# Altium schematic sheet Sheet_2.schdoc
size 305 x 189 mm
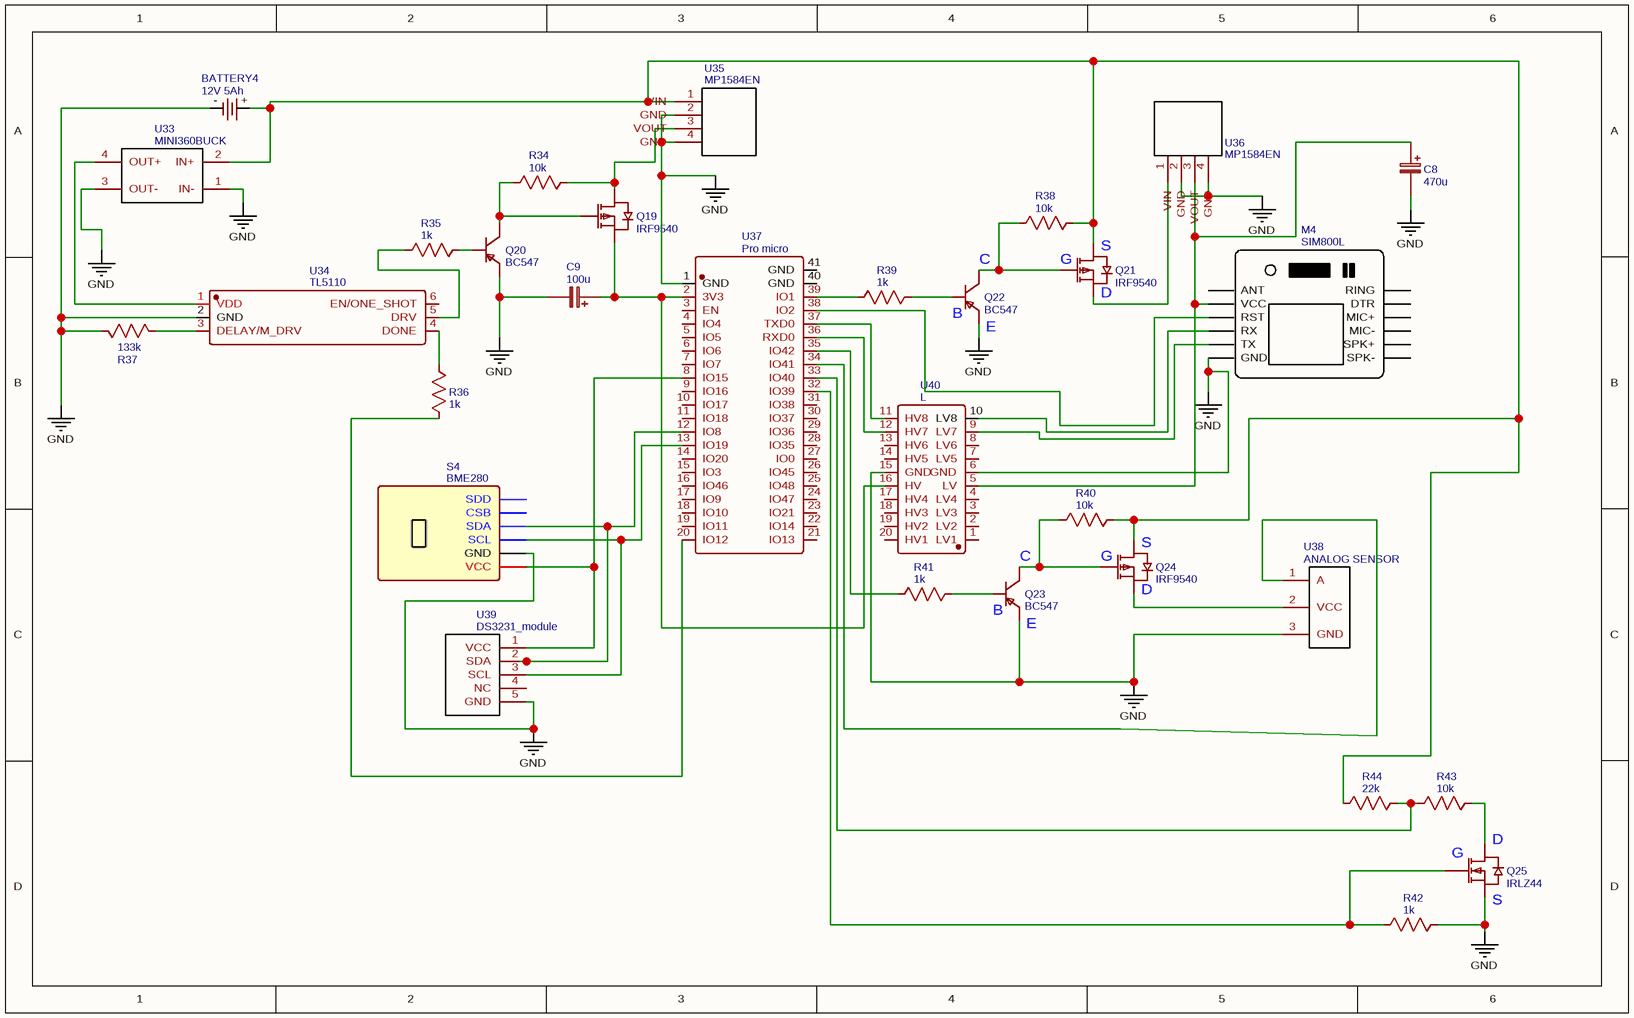
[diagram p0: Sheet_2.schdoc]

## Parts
BATTERY4  12V 5Ah  [BATTERY-SMD-MY-2032]
C8  470u  [CASE-A_3216]
C9  100u  [CASE-A_3216]
M4  SIM800L  [SIM800LMODULE_SIM800LMODULE]
Q19  IRF9540  [TO-263-2_L10.0-W9.1-P5.08-LS15.2-BR]
Q20  BC547  [SOT-23-3_L2.9-W1.6-P1.90-LS2.8-TR-CW]
Q21  IRF9540  [TO-263-2_L10.0-W9.1-P5.08-LS15.2-BR]
Q22  BC547  [SOT-23-3_L2.9-W1.6-P1.90-LS2.8-TR-CW]
Q23  BC547  [SOT-23-3_L2.9-W1.6-P1.90-LS2.8-TR-CW]
Q24  IRF9540  [TO-263-2_L10.0-W9.1-P5.08-LS15.2-BR]
Q25  IRLZ44  [TO-220-3_L10.0-W4.5-P2.54-T]
R34  10k  [R0603]
R35  1k  [R0603]
R36  1k  [R0603]
R37  133k  [R0603]
R38  10k  [R0603]
R39  1k  [R0603]
R40  10k  [R0603]
R41  1k  [R0603]
R42  1k  [R0603]
R43  10k  [R0603]
R44  22k  [R0603]
S4  BME280  [BME280]
U33  MINI360BUCK  [MINI360BUCK]
U34  TL5110  [TSOT-23-6_L2.9-W1.6-P0.95-LS2.8-BR]
U35  MP1584EN  [MP1584EN]
U36  MP1584EN  [MP1584EN]
U37  Pro micro  [WIRELM-SMD_ESP32-S3-WROOM-1U]
U38  ANALOG SENSOR  [ANALOG SENSOR V1]
U39  DS3231_module  [DS3231]
U40  L  [MPN-TH-20_L28.0-W14.0-P2.54-BL]

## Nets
GND: BATTERY4.-(BAT-) C8.2 C9.2 M4.6(GND) Q20.1(E) Q22.1(E) Q23.1(E) Q25.3(S) R37.1 R42.2 S4.2(GND) U33.1(IN-) U33.3(OUT-) U34.2(GND) U35.4(GND) U36.2(GND) U36.4(GND) U37.1(GND) U38.3(GND) U39.5(GND) U40.6(GND) U40.15(GND)
NetBATTERY4_+: BATTERY4.+(BAT+) Q21.4(D) Q24.4(D) R38.1 R40.1 R44.1 U33.2(IN+) U35.1(VIN)
NetC8_1: C8.1 M4.2(VCC) U36.3(VOUT) U40.5(LV)
NetC9_1: C9.1 Q19.3(S) U37.2(3V3) U40.16(HV)
NetM4_3: M4.3(RST) U37.38(IO2)
NetM4_4: M4.4(RX) U40.10(LV8)
NetM4_5: M4.5(TX) U40.9(LV7)
NetQ19_1: Q19.1(G) Q20.3(C) R34.2
NetQ19_4: Q19.4(D) R34.1 U35.3(VOUT)
NetQ20_2: Q20.2(B) R35.1
NetQ21_1: Q21.1(G) Q22.3(C) R38.2
NetQ21_3: Q21.3(S) U36.1(VIN)
NetQ22_2: Q22.2(B) R39.2
NetQ23_2: Q23.2(B) R41.2
NetQ23_3: Q23.3(C) Q24.1(G) R40.2
NetQ24_3: Q24.3(S) U38.2(VCC)
NetQ25_1: Q25.1(G) R42.1 U37.32(IO39)
NetQ25_2: Q25.2(D) R43.2
NetR35_2: R35.2 U34.5(DRV)
NetR36_1: R36.1 U34.4(DONE)
NetR36_2: R36.2 U37.20(IO12)
NetR37_2: R37.2 U34.3(DELAY/M_DRV)
NetR39_1: R39.1 U37.39(IO1)
NetR41_1: R41.1 U37.35(IO42)
NetR43_1: R43.1 R44.2 U37.33(IO40)
NetS4_1: S4.1(VCC) U37.8(IO15) U39.1(VCC)
NetS4_3: S4.3(SCL) U37.13(IO19) U39.3(SCL)
NetS4_4: S4.4(SDA) U37.12(IO8) U39.2(SDA)
NetU33_4: U33.4(OUT+) U34.1(VDD)
NetU37_34: U37.34(IO41) U38.1(A)
NetU37_36: U37.36(RXD0) U40.12(HV7)
NetU37_37: U37.37(TXD0) U40.11(HV8)

Not connected (* = marked no-connect by the designer): M4 1(ANT) 7(SPK-) 8(SPK+) 9(MIC-) 10(MIC+) 11(DTR) 12(RING); S4 5(CSB) 6(SDD); U34 6(EN/ONE_SHOT); U35 2(GND); U37 3(EN) 4(IO4) 5(IO5) 6(IO6) 7(IO7) 9(IO16) 10(IO17) 11(IO18) 14(IO20) 15(IO3) 16(IO46) 17(IO9) 18(IO10) 19(IO11) 21(IO13) 22(IO14) 23(IO21) 24(IO47) 25(IO48) 26(IO45) 27(IO0) 28(IO35) 29(IO36) 30(IO37) 31(IO38) 40(GND) 41(GND); U39 4(NC); U40 1(LV1) 2(LV2) 3(LV3) 4(LV4) 7(LV5) 8(LV6) 13(HV6) 14(HV5) 17(HV4) 18(HV3) 19(HV2) 20(HV1)

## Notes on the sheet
- (near Q22) C
- (near Q21) G
- (near Q21) D
- (near Q21) S
- (near Q22) B
- (near Q22) E
- (near Q23) C
- (near Q24) G
- (near Q24) S
- (near Q23) B
- (near Q23) E
- (near Q24) D
- (near Q25) G
- (near Q25) D
- (near Q25) S

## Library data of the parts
BATTERY4 = 12V 5Ah: Manufacturer: MYOUNG(美阳); Manufacturer Part: MY-2032-10; Contributor: lcsc
C8 = 470u: nameAlias: Value(F); Contributor: LCEDA_Lib
C9 = 100u: nameAlias: Value(F); Contributor: LCEDA_Lib
M4 = SIM800L: Contributor: sharad.rask
Q19 Q21 Q24 = IRF9540: Manufacturer: IR; Manufacturer Part: IRF5210STRLPBF; Paste Type: expand; Contributor: LCEDA_Lib
Q20 Q22 Q23 = BC547: Manufacturer: KEC; Manufacturer Part: 2N3906S-RTK/PS; Contributor: LCEDA_Lib
Q25 = IRLZ44: Manufacturer: Infineon(英飞凌); Manufacturer Part: IRLZ44NPBF
R34 R38 R40 R43 = 10k: nameAlias: Value(Ω); Contributor: LCEDA_Lib
R35 R36 R39 R41 R42 = 1k: nameAlias: Value(Ω); Contributor: LCEDA_Lib
R37 = 133k: nameAlias: Value(Ω); Contributor: LCEDA_Lib
R44 = 22k: nameAlias: Value(Ω); Contributor: LCEDA_Lib
U33 = MINI360BUCK: Contributor: Andrey Fedorov; sourceId: FRLFXR8qI
U34 = TL5110: Manufacturer: TI(德州仪器); Manufacturer Part: TPL5110DDCR; Contributor: lcsc; nameAlias: Value
U35 U36 = MP1584EN: Contributor: babeinlovexd
U37 = Pro micro: Manufacturer: null; Manufacturer Part: ESP32-S3-WROOM-1U; Contributor: lcsc
U38 = ANALOG SENSOR: Contributor: utbahR
U39 = DS3231_module: Contributor: retret
U40 = L: Manufacturer: null; Manufacturer Part: Level Converter 8; Contributor: LCSC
